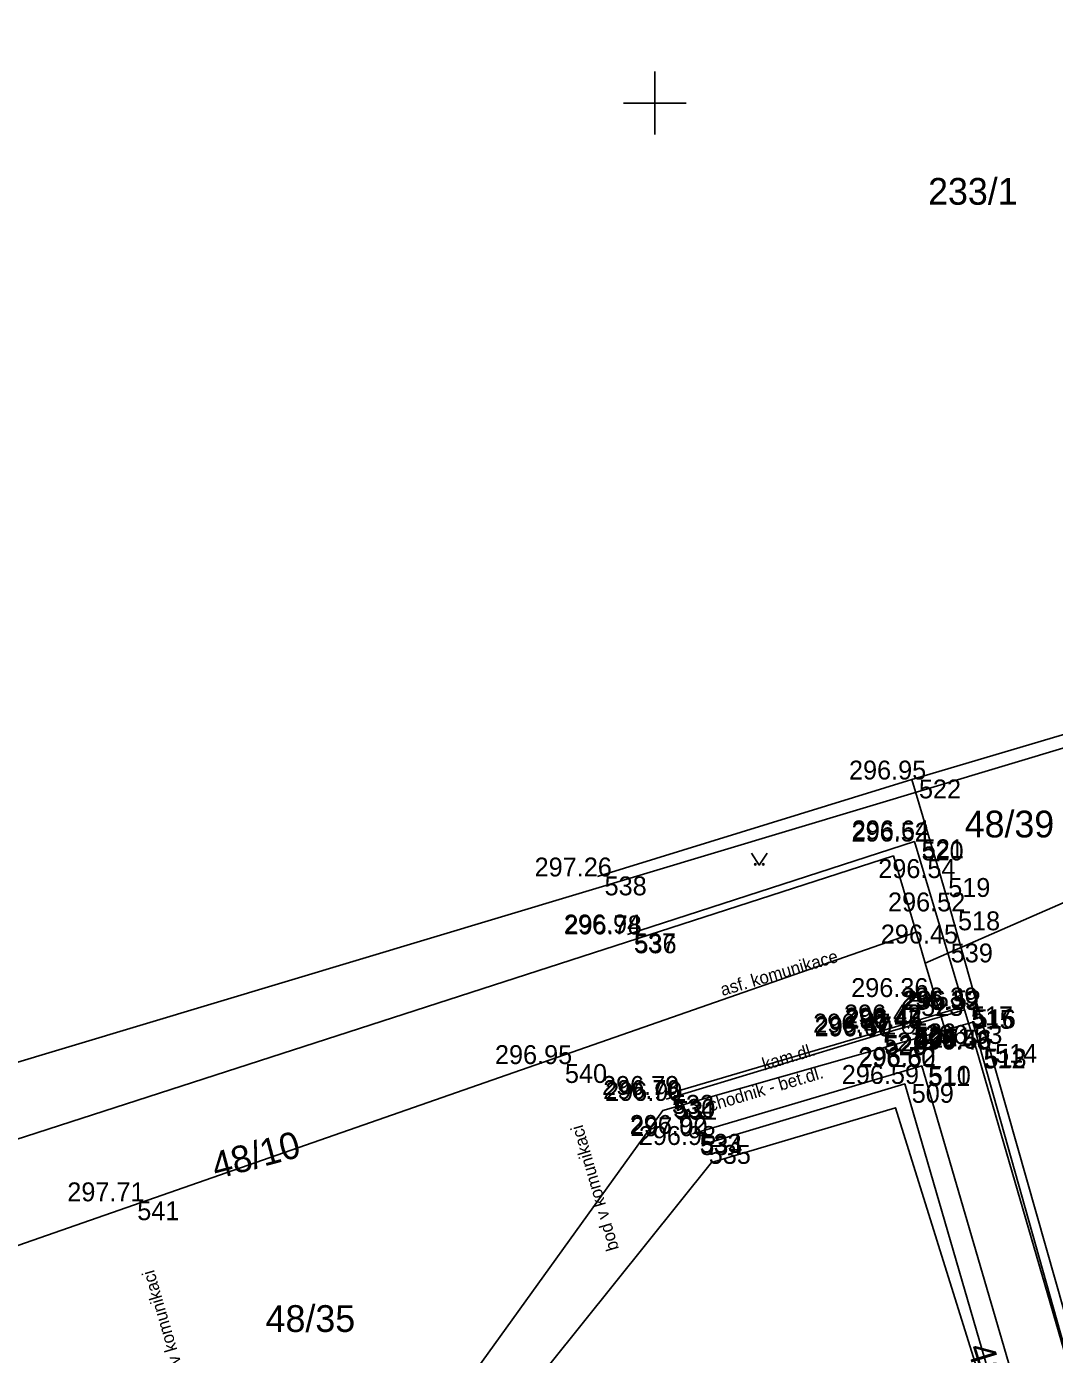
# Model space of a CAD drawing. Extents: x -599970 to -599524, y -1154772 to -1154457.
# Drawn here: x -599819.97 to -599787.3, y -1154639.75 to -1154597.57 of the extents above; entities that cross this region are included whole.
import ezdxf

# ---------------------------------------------------------------- set-up
doc = ezdxf.new("R2010")
doc.units = 0
for name, color, linetype in [('Z-KANALIZACNI SACHTY VPUSTI', 7, 'Continuous'), ('Z-KATASTRALNI MAPA', 7, 'Continuous'), ('Z-KRIZKY CTVERCOVE SITE', 7, 'Continuous'), ('Z-PEVNE BODY-CISLO', 7, 'Continuous'), ('Z-PEVNE BODY-VYSKA', 7, 'Continuous'), ('Z-PEVNE BODY-ZNACKA', 7, 'Continuous'), ('Z-PLOT DRATENY', 7, 'Continuous'), ('Z-PODROBNE BODY', 7, 'Continuous'), ('Z-PODROBNE BODY-CISLO', 7, 'Continuous'), ('Z-PODROBNE BODY-VYSKA', 7, 'Continuous'), ('Z-POPISY OBJEKTU A ZPEVNENYCH PLOCH', 7, 'Continuous'), ('Z-STROMY ZNACKY KULTUR', 7, 'Continuous'), ('Z-VSTUPY VJEZDY', 7, 'Continuous'), ('Z-ZPEVNENE PLOCHY', 7, 'Continuous')]:
    doc.layers.add(name, color=color, linetype=linetype)

msp = doc.modelspace()

# ---------------------------------------------------------------- linework, layer by layer
at = {"layer": 'Z-KANALIZACNI SACHTY VPUSTI'}
msp.add_line((-599791.885, -1154628.4), (-599791.635, -1154628.4), dxfattribs=at)
msp.add_lwpolyline([(-599791.885, -1154628.525), (-599791.635, -1154628.525), (-599791.635, -1154628.275), (-599791.885, -1154628.275)], close=True, dxfattribs=at)
at = {"layer": 'Z-KATASTRALNI MAPA'}
for p, q in [((-599779.98, -1154622.34), (-599791.41, -1154627.32)), ((-599828.05, -1154639.01), (-599791.7, -1154626.34)), ((-599791.41, -1154627.32), (-599791.7, -1154626.34)), ((-599790.77, -1154629.45), (-599791.41, -1154627.32))]:
    msp.add_line(p, q, dxfattribs=at)
for points in [[(-599782.89, -1154620.22), (-599786.61, -1154620.37), (-599830.02, -1154633.4)], [(-599791.7, -1154626.34), (-599792.42, -1154623.92), (-599829.18, -1154635.8)], [(-599784.88, -1154646.97), (-599789.9, -1154629.2), (-599790.77, -1154629.45)], [(-599809.93, -1154642.24), (-599806.3, -1154641.11), (-599799.75, -1154632.01), (-599790.77, -1154629.45)], [(-599779.65, -1154674.5), (-599784.9, -1154657), (-599786.85, -1154655.89), (-599787.57, -1154653.53), (-599785.79, -1154652.94), (-599792.35, -1154631.92), (-599798.2, -1154633.66), (-599805.39, -1154642.63)]]:
    msp.add_lwpolyline(points, dxfattribs=at)
at = {"layer": 'Z-KRIZKY CTVERCOVE SITE'}
for p, q in [((-599800, -1154601), (-599800, -1154599)), ((-599799, -1154600), (-599801, -1154600))]:
    msp.add_line(p, q, dxfattribs=at)
at = {"layer": 'Z-PEVNE BODY-ZNACKA'}
for radius in [0.188, 0.188, 0.00896, 0.00896]:
    msp.add_circle((-599791.94, -1154629.37), radius, dxfattribs=at)
at = {"layer": 'Z-PLOT DRATENY'}
for points in [[(-599741.2, -1154597.57), (-599748.19, -1154602.02), (-599750.03, -1154603.24), (-599757.54, -1154607.83), (-599759.8, -1154609.21), (-599765.35, -1154612.62), (-599767.84, -1154614.15), (-599771.68, -1154615.78), (-599777.02, -1154618.08), (-599780.14, -1154619.26), (-599783.61, -1154619.05), (-599791.83, -1154621.49)], [(-599790.9, -1154624.62), (-599791.83, -1154621.49), (-599801.82, -1154624.57)], [(-599790.59, -1154625.68), (-599789.41, -1154629.89), (-599785.15, -1154644.86), (-599782.34, -1154653.87), (-599779.13, -1154664.86), (-599776.51, -1154673.7), (-599770.19, -1154672.08), (-599762.65, -1154670.15), (-599753.18, -1154667.49), (-599743.82, -1154665.08), (-599731.66, -1154661.71), (-599725.96, -1154660.31)], [(-599785.89, -1154652.48), (-599787.79, -1154645.85), (-599792.06, -1154631.16), (-599798.51, -1154633.1)]]:
    msp.add_lwpolyline(points, dxfattribs=at)
at = {"layer": 'Z-PODROBNE BODY'}
for p, q in [((-599791.83, -1154621.49), (-599791.83, -1154621.49)), ((-599791.75, -1154623.46), (-599791.75, -1154623.46)), ((-599791.74, -1154623.39), (-599791.74, -1154623.39)), ((-599801.82, -1154624.57), (-599801.82, -1154624.57)), ((-599790.9, -1154624.62), (-599790.9, -1154624.62)), ((-599790.59, -1154625.68), (-599790.59, -1154625.68)), ((-599800.89, -1154626.38), (-599800.89, -1154626.38)), ((-599800.87, -1154626.41), (-599800.87, -1154626.41)), ((-599790.82, -1154626.7), (-599790.82, -1154626.7)), ((-599791.76, -1154628.4), (-599791.76, -1154628.4)), ((-599790.18, -1154628.7), (-599790.18, -1154628.7)), ((-599790.16, -1154628.81), (-599790.16, -1154628.81)), ((-599790.09, -1154628.79), (-599790.09, -1154628.79)), ((-599791.99, -1154629.24), (-599791.99, -1154629.24)), ((-599792.97, -1154629.53), (-599792.97, -1154629.53)), ((-599792.92, -1154629.61), (-599792.92, -1154629.61)), ((-599792.92, -1154629.65), (-599792.92, -1154629.65)), ((-599791.97, -1154629.34), (-599791.97, -1154629.34)), ((-599791.95, -1154629.41), (-599791.95, -1154629.41)), ((-599789.78, -1154630.07), (-599789.78, -1154630.07)), ((-599789.75, -1154630.04), (-599789.75, -1154630.04)), ((-599789.41, -1154629.89), (-599789.41, -1154629.89)), ((-599803.08, -1154630.53), (-599803.08, -1154630.53)), ((-599791.54, -1154630.63), (-599791.54, -1154630.63)), ((-599791.52, -1154630.59), (-599791.52, -1154630.59)), ((-599792.06, -1154631.16), (-599792.06, -1154631.16)), ((-599799.68, -1154631.51), (-599799.68, -1154631.51)), ((-599799.64, -1154631.64), (-599799.64, -1154631.64)), ((-599799.58, -1154631.7), (-599799.58, -1154631.7)), ((-599798.8, -1154632.75), (-599798.8, -1154632.75)), ((-599798.78, -1154632.82), (-599798.78, -1154632.82)), ((-599798.51, -1154633.1), (-599798.51, -1154633.1)), ((-599816.67, -1154634.89), (-599816.67, -1154634.89))]:
    msp.add_line(p, q, dxfattribs=at)
at = {"layer": 'Z-STROMY ZNACKY KULTUR'}
msp.add_lwpolyline([(-599796.93, -1154623.835), (-599796.68, -1154624.21), (-599796.43, -1154623.835)], dxfattribs=at)
for centre in [(-599796.805, -1154624.185), (-599796.555, -1154624.185)]:
    msp.add_circle(centre, 0.025, dxfattribs=at)
at = {"layer": 'Z-VSTUPY VJEZDY'}
msp.add_lwpolyline([(-599790.59, -1154625.68), (-599790.9, -1154624.62)], dxfattribs=at)
at = {"layer": 'Z-ZPEVNENE PLOCHY'}
for points in [[(-599790.16, -1154628.81), (-599790.18, -1154628.7), (-599791.75, -1154623.46), (-599800.87, -1154626.41)], [(-599790.18, -1154628.7), (-599791.99, -1154629.24), (-599792.97, -1154629.53), (-599799.68, -1154631.51)], [(-599790.16, -1154628.81), (-599791.97, -1154629.34), (-599792.92, -1154629.61), (-599799.64, -1154631.64)], [(-599776.8, -1154674.93), (-599776.98, -1154673.98), (-599779.61, -1154665.08), (-599782.84, -1154653.93), (-599785.44, -1154645), (-599789.78, -1154630.07), (-599790.16, -1154628.81)], [(-599785.05, -1154652.74), (-599787.11, -1154645.67), (-599791.52, -1154630.59), (-599798.8, -1154632.75)]]:
    msp.add_lwpolyline(points, dxfattribs=at)

# ---------------------------------------------------------------- texts
at = {"layer": 'Z-KATASTRALNI MAPA'}
for s, p in [('233/1', (-599791.316, -1154603.23)), ('48/39', (-599790.153, -1154623.33)), ('48/35', (-599812.367, -1154639.04))]:
    msp.add_text(s, height=0.85, dxfattribs=at).set_placement(p)
for s, rotation, p in [('48/10', 15, (-599813.946, -1154634.196)), ('48/37', 287, (-599790.083, -1154639.543))]:
    msp.add_text(s, height=0.85, rotation=rotation, dxfattribs=at).set_placement(p)
at = {"layer": 'Z-PEVNE BODY-CISLO'}
msp.add_text(' 4011', height=0.6, dxfattribs=at).set_placement((-599791.94, -1154629.97))
at = {"layer": 'Z-PEVNE BODY-VYSKA'}
msp.add_text('296.44 ', height=0.6, dxfattribs=at).set_placement((-599793.94, -1154629.37))
at = {"layer": 'Z-PODROBNE BODY-CISLO'}
for s, p in [(' 522', (-599791.83, -1154622.09)), (' 520', (-599791.75, -1154624.06)), (' 521', (-599791.74, -1154623.99)), (' 538', (-599801.82, -1154625.17)), (' 519', (-599790.9, -1154625.22)), (' 518', (-599790.59, -1154626.28)), (' 537', (-599800.89, -1154626.98)), (' 536', (-599800.87, -1154627.01)), (' 539', (-599790.82, -1154627.3)), (' 523', (-599791.76, -1154629)), (' 517', (-599790.18, -1154629.3)), (' 515', (-599790.16, -1154629.41)), (' 516', (-599790.09, -1154629.39)), (' 526', (-599791.99, -1154629.84)), (' 527', (-599792.97, -1154630.13)), (' 528', (-599792.92, -1154630.21)), (' 529', (-599792.92, -1154630.25)), (' 524', (-599791.97, -1154629.94)), (' 525', (-599791.95, -1154630.01)), (' 512', (-599789.78, -1154630.67)), (' 513', (-599789.75, -1154630.64)), (' 514', (-599789.41, -1154630.49)), (' 540', (-599803.08, -1154631.13)), (' 511', (-599791.54, -1154631.23)), (' 510', (-599791.52, -1154631.19)), (' 509', (-599792.06, -1154631.76)), (' 532', (-599799.68, -1154632.11)), (' 530', (-599799.64, -1154632.24)), (' 531', (-599799.58, -1154632.3)), (' 533', (-599798.8, -1154633.35)), (' 534', (-599798.78, -1154633.42)), (' 535', (-599798.51, -1154633.7)), (' 541', (-599816.67, -1154635.49))]:
    msp.add_text(s, height=0.6, dxfattribs=at).set_placement(p)
at = {"layer": 'Z-PODROBNE BODY-VYSKA'}
for s, p in [('296.95 ', (-599793.83, -1154621.49)), ('296.52 ', (-599793.75, -1154623.46)), ('296.64 ', (-599793.74, -1154623.39)), ('297.26 ', (-599803.82, -1154624.57)), ('296.54 ', (-599792.9, -1154624.62)), ('296.52 ', (-599792.59, -1154625.68)), ('296.94 ', (-599802.89, -1154626.38)), ('296.78 ', (-599802.87, -1154626.41)), ('296.45 ', (-599792.82, -1154626.7)), ('296.36 ', (-599793.76, -1154628.4)), ('296.39 ', (-599792.18, -1154628.7)), ('296.39 ', (-599792.16, -1154628.81)), ('296.52 ', (-599792.09, -1154628.79)), ('296.42 ', (-599793.99, -1154629.24)), ('296.42 ', (-599793.97, -1154629.34)), ('296.45 ', (-599793.95, -1154629.41)), ('296.47 ', (-599794.97, -1154629.53)), ('296.47 ', (-599794.92, -1154629.61)), ('296.60 ', (-599794.92, -1154629.65)), ('296.48 ', (-599791.78, -1154630.07)), ('296.56 ', (-599791.75, -1154630.04)), ('296.53 ', (-599791.41, -1154629.89)), ('296.95 ', (-599805.08, -1154630.53)), ('296.60 ', (-599793.54, -1154630.63)), ('296.52 ', (-599793.52, -1154630.59)), ('296.79 ', (-599801.68, -1154631.51)), ('296.59 ', (-599794.06, -1154631.16)), ('296.76 ', (-599801.64, -1154631.64)), ('296.90 ', (-599801.58, -1154631.7)), ('296.92 ', (-599800.8, -1154632.75)), ('297.00 ', (-599800.78, -1154632.82)), ('296.98 ', (-599800.51, -1154633.1)), ('297.71 ', (-599818.67, -1154634.89))]:
    msp.add_text(s, height=0.6, dxfattribs=at).set_placement(p)
at = {"layer": 'Z-POPISY OBJEKTU A ZPEVNENYCH PLOCH'}
for s, rotation, p in [('asf. komunikace', 16.4404, (-599797.85, -1154628.37)), ('kam.dl.', 16.8087, (-599796.52, -1154630.74)), ('chodnik - bet.dl.', 16.5258, (-599798.23, -1154632.04)), ('bod v komunikaci', 106.301, (-599801.14, -1154636.4)), ('bod v komunikaci', 106.301, (-599814.76, -1154641.01))]:
    msp.add_text(s, height=0.4, rotation=rotation, dxfattribs=at).set_placement(p)

doc.saveas('drawing.dxf')
